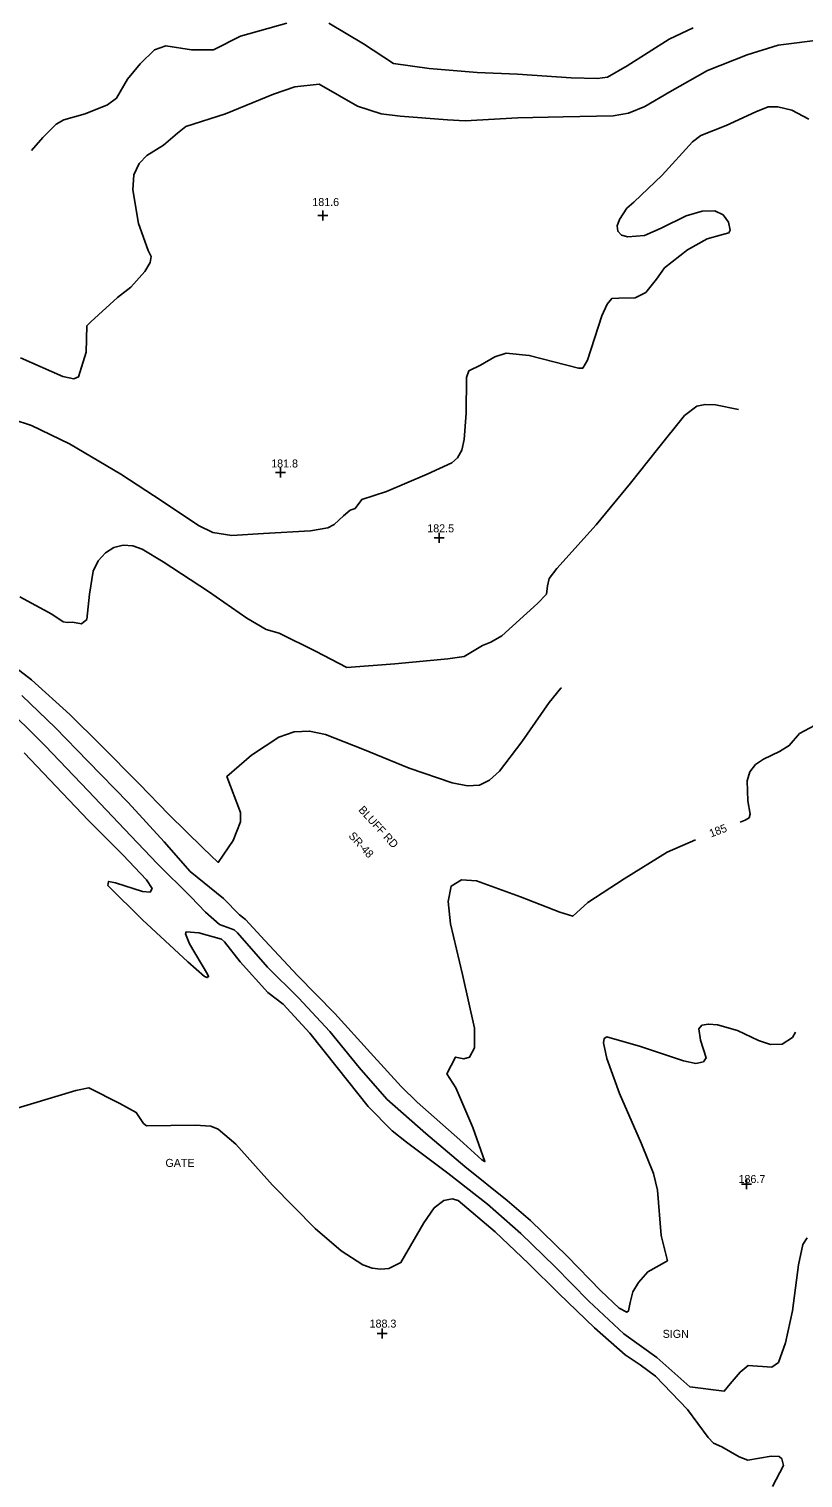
# Model space of a CAD drawing. Extents: x 1475150 to 2003689, y 770235 to 1112803.
# Drawn here: x 1992157.7 to 1992351.2, y 779596.3 to 779958.6 of the extents above; entities that cross this region are included whole.
import ezdxf

# ---------------------------------------------------------------- set-up
doc = ezdxf.new("R2010")
doc.units = 0
for name, color, linetype in [('RD_DTM_Major1', 7, 'Continuous'), ('RD_DTM_Major1_Lbl', 7, 'Continuous'), ('RD_DTM_Minor1', 7, 'Continuous'), ('RD_DTM_Spot_Elev', 7, 'Continuous'), ('RD_TX_Misc1', 7, 'Continuous')]:
    doc.layers.add(name, color=color, linetype=linetype)

msp = doc.modelspace()

# ---------------------------------------------------------------- linework, layer by layer
at = {"layer": 'RD_DTM_Major1'}
for points in [[(1992222.17, 779960.02), (1992210.57, 779956.77), (1992203.82, 779953.33), (1992198.31, 779953.37), (1992191.94, 779954.39), (1992189.11, 779953.34), (1992185.52, 779949.88), (1992182.36, 779946.06), (1992179.57, 779941.26), (1992177.39, 779939.66), (1992171.79, 779937.38), (1992166.45, 779935.91), (1992164.51, 779934.82), (1992161.15, 779931.48), (1992158.37, 779928.2)], [(1992323.77, 779958.85), (1992317.76, 779956.04), (1992307.28, 779949.39), (1992302.39, 779946.56), (1992299.88, 779946.2), (1992293.24, 779946.39), (1992279.83, 779947.3), (1992269.79, 779947.7), (1992257.8, 779948.72), (1992248.88, 779949.95), (1992241.37, 779954.89), (1992232.66, 779960.06)], [(1992324.37, 779755.87), (1992317.27, 779752.79), (1992306.52, 779746.16), (1992297.46, 779740.2), (1992293.66, 779736.8), (1992290.47, 779737.8), (1992280.59, 779741.65), (1992269.57, 779745.65), (1992265.84, 779745.9), (1992263.3, 779744.33), (1992262.49, 779740.44), (1992263.07, 779734.86), (1992266.07, 779722.24), (1992269.08, 779708.82), (1992269.09, 779703.92), (1992267.87, 779701.56), (1992266.44, 779701.15), (1992264.34, 779701.56), (1992262.19, 779697.39), (1992264.46, 779693.92), (1992268.73, 779684), (1992271.69, 779675.43), (1992270.97, 779675.91), (1992265.43, 779680.85), (1992254.79, 779690.29), (1992250.73, 779694.22), (1992243.09, 779702.61), (1992234.17, 779712.47), (1992224.84, 779721.99), (1992216.71, 779730.7), (1992211.86, 779735.99), (1992210.37, 779737.16), (1992206.39, 779741.25), (1992198.05, 779747.96), (1992191.48, 779755.4), (1992182.54, 779765.19), (1992172.41, 779775.58), (1992164.36, 779783.87), (1992155.93, 779791.93)], [(1992354.13, 779784.49), (1992350.33, 779782.44), (1992347.8, 779779.46), (1992345.35, 779777.96), (1992341.33, 779776.07), (1992339.38, 779774.72), (1992337.95, 779772.92), (1992337.27, 779770.61), (1992337.48, 779765.6), (1992338.02, 779762.26), (1992337.76, 779761.42), (1992336.79, 779760.76), (1992335.53, 779760.28)]]:
    msp.add_lwpolyline(points, dxfattribs=at)
at = {"layer": 'RD_DTM_Minor1'}
for points in [[(1992356.28, 779955.98), (1992345.07, 779954.51), (1992337.29, 779952.15), (1992327.38, 779948.22), (1992317.98, 779942.91), (1992311.72, 779939.18), (1992307.65, 779937.54), (1992303.78, 779936.91), (1992291.28, 779936.64), (1992279.94, 779936.33), (1992266.77, 779935.63), (1992262.36, 779935.84), (1992250.54, 779936.75), (1992245.75, 779937.34), (1992239.88, 779939.26), (1992230.23, 779944.75), (1992224.18, 779944.16), (1992218.83, 779942.31), (1992206.85, 779937.36), (1992196.9, 779934.17), (1992194.84, 779932.55), (1992191.39, 779929.55), (1992187.18, 779926.95), (1992185.23, 779924.94), (1992183.97, 779922.11), (1992183.7, 779918.34), (1992185.14, 779909.98), (1992187.53, 779903.17), (1992188.26, 779901.67), (1992187.98, 779900.21), (1992186.67, 779897.99), (1992183.15, 779894.06), (1992179.84, 779891.44), (1992173.15, 779885.37), (1992172.22, 779884.35), (1992171.98, 779877.78), (1992170.1, 779871.62), (1992168.9, 779871.16), (1992166.15, 779871.74), (1992155.6, 779876.35)], [(1992352.66, 779936), (1992348.46, 779938.28), (1992344.91, 779939.16), (1992342.55, 779939.1), (1992339.44, 779937.83), (1992332.03, 779934.44), (1992325.68, 779931.96), (1992323.61, 779930.37), (1992316, 779922.05), (1992308.93, 779915.3), (1992307.23, 779913.75), (1992305.36, 779910.93), (1992304.81, 779909.36), (1992304.91, 779908.01), (1992305.83, 779907.08), (1992307.42, 779906.61), (1992311.59, 779906.95), (1992315.78, 779908.75), (1992322, 779911.89), (1992326.03, 779913.03), (1992329.18, 779913.12), (1992331.26, 779912.16), (1992332.58, 779910.33), (1992333, 779908.33), (1992332.72, 779907.64), (1992330.88, 779907.12), (1992327.31, 779906.16), (1992322.4, 779903.37), (1992316.65, 779898.88), (1992314.58, 779896.05), (1992311.94, 779892.71), (1992309.24, 779891.41), (1992305.18, 779891.29), (1992303.41, 779891.17), (1992302.3, 779889.81), (1992300.95, 779886.88), (1992297.32, 779875.78), (1992296.19, 779873.79), (1992295.12, 779873.8), (1992282.81, 779876.98), (1992277.04, 779877.55), (1992274.21, 779876.64), (1992270.57, 779874.54), (1992267.65, 779873.14), (1992267.14, 779871.47), (1992267.02, 779862.57), (1992266.55, 779856), (1992265.9, 779853.29), (1992264.87, 779851.38), (1992263.46, 779850.1), (1992257.3, 779847.28), (1992247.08, 779842.97), (1992240.91, 779840.98), (1992239.23, 779838.72), (1992238.03, 779838.31), (1992236.38, 779836.86), (1992234.04, 779834.72), (1992232.43, 779833.87), (1992228.12, 779833.16), (1992216.36, 779832.47), (1992208.4, 779831.98), (1992203.72, 779832.69), (1992200.14, 779834.48), (1992191.02, 779840.56), (1992180.69, 779847.31), (1992167.82, 779854.91), (1992158.32, 779859.42), (1992153.75, 779860.92)], [(1992335.15, 779863.45), (1992329.32, 779864.64), (1992326.74, 779864.73), (1992324.68, 779864.27), (1992321.63, 779861.99), (1992314.9, 779853.54), (1992308.07, 779845.03), (1992299.52, 779834.62), (1992289.7, 779823.71), (1992287.77, 779821.23), (1992287.38, 779819.36), (1992287.08, 779817.33), (1992284.89, 779814.93), (1992275.91, 779806.84), (1992273.22, 779805.29), (1992271.09, 779804.44), (1992266.55, 779801.73), (1992262.48, 779801.11), (1992249.17, 779799.87), (1992237.16, 779798.98), (1992229.33, 779803.04), (1992220.27, 779807.52), (1992217.02, 779808.45), (1992212.19, 779811.29), (1992202.59, 779817.96), (1992191.29, 779825.37), (1992186, 779828.53), (1992183.69, 779829.35), (1992181.3, 779829.57), (1992178.96, 779828.97), (1992176.82, 779827.6), (1992175.04, 779825.59), (1992173.76, 779823.08), (1992172.83, 779817.27), (1992172.2, 779810.97), (1992170.88, 779809.92), (1992168.57, 779810.3), (1992167.32, 779810.24), (1992166.26, 779810.38), (1992163.4, 779812.29), (1992155.42, 779816.65)], [(1992290.82, 779793.86), (1992290.7, 779793.77), (1992287.77, 779790.23), (1992280.97, 779780.37), (1992275.34, 779773.05), (1992272.86, 779770.77), (1992270.36, 779769.58), (1992267.39, 779769.39), (1992263.55, 779770.13), (1992252.81, 779773.77), (1992241.15, 779778.53), (1992231.83, 779782.24), (1992227.86, 779783.06), (1992224.03, 779782.87), (1992220.21, 779781.53), (1992213.34, 779777.07), (1992207.17, 779771.69), (1992210.62, 779762.74), (1992210.57, 779760.42), (1992208.79, 779755.73), (1992205.03, 779750.24), (1992201.25, 779753.79), (1992192.71, 779762.2), (1992185.3, 779769.86), (1992175.57, 779779.6), (1992167.95, 779787.19), (1992158.32, 779795.87), (1992149.92, 779802.27)], [(1992349.33, 779707.77), (1992348.61, 779706.5), (1992346.02, 779704.77), (1992343.07, 779704.69), (1992340.14, 779705.72), (1992334.85, 779708.2), (1992329.88, 779709.6), (1992327.61, 779709.84), (1992325.97, 779709.56), (1992325.22, 779708.66), (1992325.58, 779705.81), (1992327.02, 779701.41), (1992326.35, 779700.37), (1992324.45, 779700.01), (1992321.37, 779700.63), (1992310.61, 779704.19), (1992302.19, 779706.64), (1992301.54, 779706.22), (1992301.35, 779705.15), (1992302.17, 779701.26), (1992305.4, 779692.45), (1992310.89, 779679.91), (1992313.9, 779672.48), (1992314.9, 779668.28), (1992315.81, 779656.97), (1992317.35, 779650.64), (1992312.46, 779647.88), (1992310.14, 779645.22), (1992308.72, 779642.86), (1992308.02, 779640.21), (1992307.64, 779638.13), (1992307.17, 779637.77), (1992305.3, 779638.77), (1992300.69, 779643.13), (1992292.31, 779651.82), (1992283.07, 779660.72), (1992277.27, 779665.68), (1992266.69, 779674.25), (1992256.94, 779682.47), (1992247.22, 779691.04), (1992240.3, 779699), (1992232.9, 779708.01), (1992225.11, 779716.42), (1992217.33, 779724.09), (1992209.84, 779732.66), (1992209, 779733.39), (1992205.32, 779734.7), (1992201.82, 779737.82), (1992198.21, 779741.63), (1992189.73, 779749.97), (1992181.64, 779758.59), (1992172.55, 779768.13), (1992161.76, 779779.39), (1992150.75, 779790.26)], [(1992352.3, 779656.41), (1992351.23, 779654.73), (1992350.11, 779649.61), (1992348.65, 779638.16), (1992346.87, 779630.13), (1992345.1, 779625.26), (1992343.48, 779624.06), (1992337.49, 779624.44), (1992335.52, 779622.84), (1992333.01, 779619.89), (1992331.54, 779618.07), (1992322.98, 779619.11), (1992314.71, 779626.44), (1992306.42, 779632.35), (1992297.7, 779640.56), (1992289.2, 779649.23), (1992280.7, 779657.46), (1992272.32, 779664.82), (1992262.47, 779672.53), (1992252.14, 779680.3), (1992248.5, 779683.13), (1992242.54, 779689.18), (1992234.81, 779698.96), (1992227.92, 779707.53), (1992221.23, 779714.79), (1992217.47, 779717.71), (1992210.55, 779725.36), (1992206.57, 779730.38), (1992205.86, 779731.09), (1992200.17, 779732.63), (1992196.99, 779732.86), (1992196.87, 779732.42), (1992197.85, 779729.91), (1992202.32, 779722.27), (1992202.63, 779721.71), (1992202.3, 779721.44), (1992201.56, 779721.74), (1992197.4, 779725.42), (1992186.12, 779735.92), (1992177.47, 779744.5), (1992177.64, 779745.47), (1992179.37, 779745.13), (1992186.14, 779742.95), (1992188.01, 779742.8), (1992188.49, 779743.68), (1992187.1, 779745.87), (1992181.2, 779752.15), (1992172.61, 779760.7), (1992166.1, 779767.54), (1992156.52, 779777.59)], [(1992343.59, 779594.25), (1992346.34, 779599.46), (1992345.92, 779601.16), (1992345.32, 779601.71), (1992343.29, 779601.79), (1992337.41, 779600.81), (1992335.31, 779601.61), (1992330.94, 779604.18), (1992328.89, 779605.05), (1992327.56, 779606.49), (1992322.4, 779613.51), (1992314.38, 779621.78), (1992310.56, 779624.68), (1992306.8, 779627.15), (1992299.13, 779633.85), (1992290.23, 779642.48), (1992282.64, 779650.01), (1992274.28, 779657.92), (1992265.04, 779665.71), (1992263.56, 779666.1), (1992261.48, 779665.74), (1992259, 779663.86), (1992256.44, 779660.12), (1992250.69, 779650.24), (1992247.65, 779648.76), (1992245.71, 779648.53), (1992243.55, 779648.81), (1992241.19, 779649.67), (1992235.8, 779653.12), (1992229.31, 779658.69), (1992218.59, 779669.53), (1992209.43, 779679.8), (1992205.03, 779683.59), (1992203.21, 779684.34), (1992199.24, 779684.57), (1992187.11, 779684.38), (1992186.39, 779685), (1992184.52, 779687.76), (1992180.45, 779689.98), (1992172.71, 779693.86), (1992169.47, 779693.26), (1992158.11, 779689.77), (1992147.42, 779686.67)]]:
    msp.add_lwpolyline(points, dxfattribs=at)
at = {"layer": 'RD_DTM_Spot_Elev'}
for p, q in [((1992229.91, 779911.93), (1992232.41, 779911.93)), ((1992231.16, 779910.68), (1992231.16, 779913.18)), ((1992220.57, 779846.44), (1992220.57, 779848.94)), ((1992219.32, 779847.69), (1992221.82, 779847.69)), ((1992259, 779831.39), (1992261.5, 779831.39)), ((1992260.25, 779830.14), (1992260.25, 779832.64)), ((1992337.11, 779668.55), (1992337.11, 779671.05)), ((1992335.86, 779669.8), (1992338.36, 779669.8)), ((1992244.73, 779632.48), (1992247.23, 779632.48)), ((1992245.98, 779631.23), (1992245.98, 779633.73))]:
    msp.add_line(p, q, dxfattribs=at)

# ---------------------------------------------------------------- texts
at = {"layer": 'RD_DTM_Major1_Lbl'}
msp.add_text('185', height=2, rotation=20.7038, dxfattribs=at).set_placement((1992328.25, 779756.46))
at = {"layer": 'RD_TX_Misc1'}
for s, p in [('181.6', (1992228.56, 779914.32)), ('181.8', (1992218.28, 779848.96)), ('182.5', (1992257.3, 779832.75)), ('GATE', (1992191.84, 779674.12)), ('186.7', (1992335.12, 779670.09)), ('188.3', (1992242.88, 779633.95)), ('SIGN', (1992316.15, 779631.39))]:
    msp.add_text(s, height=2, dxfattribs=at).set_placement(p)
for s, rotation, p in [('BLUFF RD', 312.4362, (1992239.95, 779763.25)), ('SR-48', 312.436, (1992237.49, 779756.75))]:
    msp.add_text(s, height=2, rotation=rotation, dxfattribs=at).set_placement(p)

doc.saveas('drawing.dxf')
